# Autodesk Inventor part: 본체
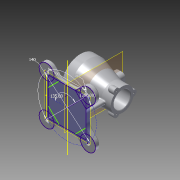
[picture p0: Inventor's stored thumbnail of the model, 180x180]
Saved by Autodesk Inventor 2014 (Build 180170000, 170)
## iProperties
Created: 2018-03
Part Number: 본체
Material: 알루미늄 6061
Document SubType Name: Modeling
Designer: kb542
Density: 2.71 g/cm^3
Appearance: 알루미늄 - 평지
Mass: 1006.72 g
Surface Area: 849.759 cm^2
Volume: 371.482 cm^3
Author: kb542
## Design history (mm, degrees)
sketch "스케치1"
  geometry: L1 (0, 0)-(100, 0); L2 (0, 35)-(23, 35); L3 (23, 35)-(23, 26); L4 (23, 26)-(70, 26); L5 (70, 26)-(70, 20); L6 (70, 20)-(100, 20); L7 (0, 35)-(0, 45); L8 (0, 45)-(20, 45); L9 (20, 45)-(77, 27.5); L10 (77, 27.5)-(100, 27.5); L11 (100, 27.5)-(100, 20); 1 further point
  constraints: 22 end point, 4 parallel, 3 perpendicular, 2 vertical alignment, 1 coincident, 1 horizontal, 1 vertical
  dimensions: "d0" = 100 distance of L1.start L1.end; "d1" = 20 distance of L7.end L8.end; "d3" = 77 distance from line of L9.end L7; "d4" = 40 diameter of L6 L1; "d5" = 55 diameter of L10 L1; "d6" = 30 distance of L5.end L6.end; "d7" = 23 distance of L2.start L2.end; "d8" = 52 diameter of L4 L1; "d9" = 70 diameter of L2 L1; "d10" = 90 diameter of L8 L1
revolve "회전1" sketch "스케치1" stored, may be unused: angle "d11" = 90 deg
sketch "스케치2"
  geometry: C1 r 7 at (0, 27.5); 1 further point
  constraints: 2 vertical alignment, 1 centre point, 1 other
  dimensions: "d13" = 7 radius of C1
extrude "돌출1" join sketch "스케치2" distance "d14" = 15; taper "d15" = 0 deg
hole "구멍1" diameter "d18" = 3.242; stored, may be unused: countersink angle "d22" = 90 deg, drill point angle "d24" = 118 deg; dims "d16" = 10, "d17" = 10, "d19" = 9, "d20" = 4, "d21" = 2, "d23" = 11
fillet "모깎기1" dims "d25" = 3, "d26" = 1
fillet "모깎기2" dims "d30" = 3
chamfer "모따기1" distance "d31" = 1; stored, may be unused: second distance "d32" = 2, angle "d33" = 45 deg
fillet "모깎기3" dims "d34" = 3
node "작업 평면1"
sketch "스케치3"
  geometry: L1 (-62.5, 12.5)-(-37.5, 12.5); L2 (-37.5, 12.5)-(-37.5, -12.5); L3 (-37.5, -12.5)-(-62.5, -12.5); L4 (-62.5, -12.5)-(-62.5, 12.5); L5 (0, 45)-(0, -45) reference; L6 (-42.5, 7.5)-(-57.5, 7.5); L7 (-57.5, 7.5)-(-57.5, -7.5); L8 (-57.5, -7.5)-(-42.5, -7.5); L9 (-42.5, -7.5)-(-42.5, 7.5); L10 (-62.5, 12.5)-(-37.5, -12.5); L11 (-37.5, 12.5)-(-62.5, -12.5); 4 further points
  constraints: 20 end point, 4 parallel, 4 perpendicular, 3 midpoint, 1 horizontal, 1 horizontal alignment, 1 point on line, 3 other
  dimensions: "d36" = 25 distance of L1.start L1.end; "d37" = 15 distance of L6.start L6.end; "d38" = 50 distance from line of point (-50, 0) L5
extrude "돌출2" join sketch "스케치3" stored distance "d39" = 15; taper "d40" = 0 deg
extrude "돌출3" cut sketch "스케치3" stored distance "d41" = 15; taper "d42" = 0 deg
fillet "모깎기4" dims "d43" = 8, "d44" = 3
fillet "모깎기5" dims "d45" = 1
chamfer "모따기2" distance "d46" = 1; stored, may be unused: second distance "d47" = 2, angle "d48" = 45 deg
sketch "스케치4" dims "d49" = 80
  geometry: C1 r 45 at (0, 0) reference; C2 r 36 at (0, 0) reference; 2 further points
  constraints: 2 vertical alignment, 1 coincident, 2 other
hole "구멍2" sketch "스케치4" at (0, 40) diameter "d50" = 3.242; stored, may be unused: countersink angle "d54" = 90 deg, drill point angle "d56" = 118 deg; dims "d51" = 9, "d52" = 4, "d53" = 2, "d55" = 11
node "작업 평면2"
node "작업 평면3"
sketch "스케치5" dims "d62" = 140
  geometry: L1 (0, 45)-(0, -45) reference; L2 (-50, -98)-(-50, 98) reference; L3 (-95, 45)-(-5, 45); L4 (-5, 45)-(-5, -45); L5 (-5, -45)-(-95, -45); L6 (-95, -45)-(-95, 45); L7 (-5, 0)-(-50, 0); L8 (-50, 0)-(-99.497, 49.497); L9 (-30.456, 45)-(-5, 19.544); L10 (-95, -19.544)-(-69.544, -45); L11 (-30.456, -45)-(-5, -19.544); L12 (-50, 0)-(-99.497, 49.497); L13 (-112.225, 36.77)-(-95, 19.544); L14 (-95, 19.544)-(-69.544, 45); L15 (-86.77, 62.225)-(-69.544, 45); L16 (-50, 25.456)-(-44.088, 19.544); C1 r 18 at (-99.497, -49.497); C2 r 18 at (-0.503, -49.497); C3 r 18 at (-0.503, 49.497); A1 r 18 centre (-99.497, 49.497) between (-86.77, 62.225) and (-112.225, 36.77); 2 further points
  constraints: 28 end point, 6 parallel, 4 centre point, 4 perpendicular, 3 midpoint, 3 point on line, 3 tangent, 2 coincident, 2 point on circle, 1 horizontal, 1 horizontal alignment, 1 vertical alignment, 12 other
  dimensions: "d61" = 90 distance of L3.start L3.end; "d63" = 135 deg angle of L8 L7; "d64" = 36 diameter of A1; "d67" = 360 deg dimension on L7.end A1.centre (derived)
extrude "돌출4" join sketch "스케치5" distance "d69" = 12; taper "d70" = 0 deg
extrude "돌출6" join sketch "스케치5" distance "d107" = 12; taper "d108" = 0 deg
fillet "모깎기6" dims "d71" = 25
sketch "스케치6"
  geometry: L1 (-70, -56.65)-(-70, -36.312) reference; L2 (-70, -42)-(-70, -56.65) reference; L3 (-70, -56.65)-(-70, -42) reference; L4 (-70, -36.312)-(-70, -56.65) reference; L5 (-70, -11.7)-(-70, -36.312) reference; L6 (-70, 11.7)-(-70, -11.7) reference; L7 (-70, 36.312)-(-70, 11.7) reference; L8 (-70, 56.65)-(-70, 36.312) reference; L9 (-70, 42)-(-70, 56.65) reference; L10 (-70, 56.65)-(-70, 42) reference; L11 (-70, 36.312)-(-70, 56.65) reference; L12 (-70, 11.7)-(-70, 36.312) reference; L13 (-70, -11.7)-(-70, 11.7) reference; L14 (-70, -36.312)-(-70, -11.7) reference; L15 (0, 0)-(-70, 0); L16 (-70, -24)-(-19.496, -19.581); L17 (-70, 24)-(-19.496, 19.581); L18 (-70, 24)-(-70, -24); C1 r 44.868 at (0, 0) reference; C2 r 35 at (0, 0) reference; A1 r 40.024 centre (0, 0) between (39.782, -4.395) and (39.782, 4.395) reference; A2 r 31.735 centre (0, 0) between (31.433, -4.368) and (31.433, 4.368) reference; A3 r 27.632 centre (0, 0) between (-19.496, 19.581) and (-19.496, -19.581); 6 further points
  constraints: 8 end point, 2 point on circle, 2 symmetric about line, 1 centre point, 1 coincident, 1 collinear, 1 midpoint, 1 point on line, 8 other
  dimensions: "d75" = 24 distance from line of L16.start L15; "d76" = 95 deg angle of L5 L16
extrude "돌출5" join sketch "스케치6" stored distance "d77" = 8; taper "d78" = 0 deg
fillet "모깎기10" dims "d109" = 25
feature "리브1" dims "d80" = 1, "d81" = 8, "d82" = 0, "d83" = 0, "d84" = 1, "d85" = 1
chamfer "모따기3" distance "d86" = 3; stored, may be unused: second distance "d87" = 2, angle "d88" = 45 deg
fillet "모깎기8" dims "d89" = 3
fillet "모깎기9" dims "d90" = 3
node "작업 평면4"
sketch "스케치8"
  geometry: L1 (-50, -94.496)-(-50, 94.496) reference; 2 further points
  constraints: 1 point on line, 1 other
  dimensions: "d92" = 35 vertical distance of point (-50, 35) point (0, 0)
feature "엠보싱1" sketch "스케치8" dims "d93" = 0.5, "d94" = 0
sketch "스케치9"
  geometry: A1 r 15 centre (0.503, -49.497) between (-10.104, -38.891) and (11.109, -60.104) reference; A2 r 15 centre (99.497, -49.497) between (88.891, -60.104) and (110.104, -38.891) reference; A3 r 15 centre (99.497, 49.497) between (110.104, 38.891) and (88.891, 60.104) reference; A4 r 15 centre (0.503, 49.497) between (11.109, 60.104) and (-10.104, 38.891) reference; 13 further points
  constraints: 4 coincident
hole "구멍3" sketch "스케치9" at (0.503, 49.497), (99.497, 49.497), (99.497, -49.497), (0.503, -49.497) diameter "d95" = 10; stored, may be unused: countersink angle "d99" = 90 deg, drill point angle "d101" = 118 deg; dims "d96" = 6, "d97" = 4, "d98" = 2, "d100" = 8
node "솔리드1"
pattern_circular "원형 패턴1" dims "d28" = 360 deg
pattern_circular "원형 패턴2" dims angle "d58" = 360 deg
mirror "대칭2"
mirror "대칭3"
mirror "대칭1"
node "투영된 루프1"
sketch "스케치7"
  geometry: L1 (13, -45)-(13, -70); L2 (20.43, -44.868)-(76.57, -27.632) reference; L3 (46, -70)-(54, -70) reference; L4 (54, -70)-(46, -70) reference; L5 (50, 68)-(50, -93) reference; L6 (0, -45)-(19.55, -45) reference; 1 further point
  constraints: 2 end point, 1 perpendicular, 1 point on line, 1 vertical
  dimensions: "d79" = 37 distance between parallel lines of L1 L5
node "투영된 루프3"
other parameters: "d35" = 45, "d60" = -82, "d91" = 21.75
